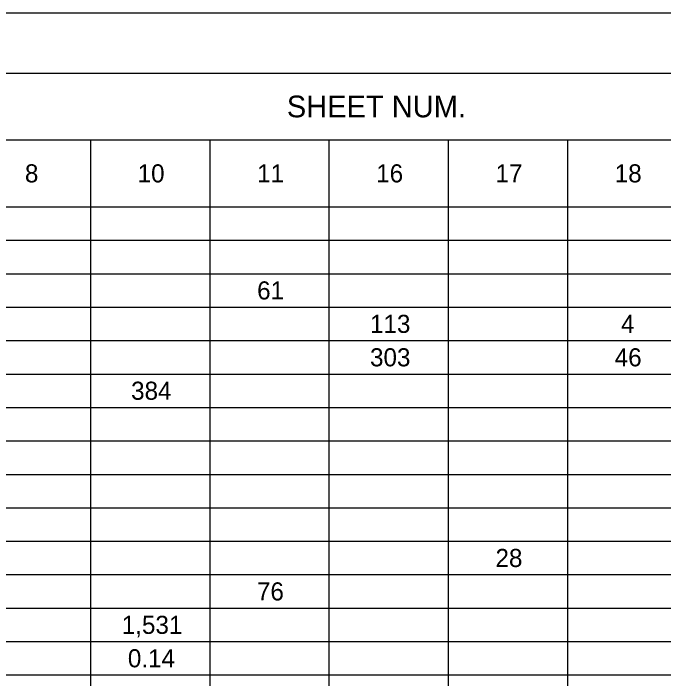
# Model space of a CAD drawing. Extents: x 0 to 44.3, y 0 to 22.
# Drawn here: x 5.16 to 10.6, y 16.43 to 22 of the extents above; entities that cross this region are included whole.
import ezdxf

# ---------------------------------------------------------------- set-up
doc = ezdxf.new("R2010")
doc.units = 0
for name, color, linetype in [('SH_Border', 7, 'Continuous'), ('SH_Cut_Line', 7, 'Continuous'), ('SH_Text', 7, 'Continuous')]:
    doc.layers.add(name, color=color, linetype=linetype)

msp = doc.modelspace()

# ---------------------------------------------------------------- linework, layer by layer
at = {"layer": 'SH_Border'}
msp.add_lwpolyline([(1.5, 21.5), (33.5, 21.5), (33.5, 0.5), (1.5, 0.5)], close=True, dxfattribs=at)
at = {"layer": 'SH_Cut_Line'}
msp.add_lwpolyline([(0, 0), (34, 0), (34, 22), (0, 22)], close=True, dxfattribs=at)
at = {"layer": 'SH_Text'}
for p, q in [((1.5, 21.5), (32, 21.5)), ((1.5, 20.94), (15.7846, 20.94)), ((5.8034, 20.94), (5.8034, 0.5)), ((6.8015, 20.94), (6.8015, 0.5)), ((7.7996, 20.94), (7.7996, 0.5)), ((8.7977, 20.94), (8.7977, 0.5)), ((9.7959, 20.94), (9.7959, 0.5)), ((1.5, 20.38), (32, 20.38)), ((1.5, 20.1), (32, 20.1)), ((1.5, 19.82), (32, 19.82)), ((1.5, 19.54), (32, 19.54)), ((1.5, 19.26), (32, 19.26)), ((1.5, 18.98), (32, 18.98)), ((1.5, 18.7), (32, 18.7)), ((1.5, 18.42), (32, 18.42)), ((1.5, 18.14), (32, 18.14)), ((1.5, 17.86), (32, 17.86)), ((1.5, 17.58), (32, 17.58)), ((1.5, 17.3), (32, 17.3)), ((1.5, 17.02), (32, 17.02)), ((1.5, 16.74), (32, 16.74)), ((1.5, 16.46), (32, 16.46))]:
    msp.add_line(p, q, dxfattribs=at)

# ---------------------------------------------------------------- texts
for s, height, p in [('SHEET NUM.', 0.18184, (7.4467, 21.1291)), ('8', 0.1515, (5.2546, 20.5842)), ('10', 0.15153, (6.198, 20.5842)), ('11', 0.15153, (7.1982, 20.5842)), ('16', 0.15153, (8.1948, 20.5842)), ('17', 0.15153, (9.1936, 20.5842)), ('18', 0.15153, (10.1912, 20.5842)), ('61', 0.15153, (7.1982, 19.6042)), ('113', 0.15153, (8.143, 19.3242)), ('4', 0.1515, (10.2439, 19.3242)), ('303', 0.15153, (8.143, 19.0442)), ('46', 0.15153, (10.191, 19.0442)), ('384', 0.15153, (6.1433, 18.7642)), ('28', 0.15153, (9.1931, 17.3642)), ('76', 0.15153, (7.1966, 17.0842)), ('1,531', 0.15153, (6.0653, 16.8042)), ('0.14', 0.15153, (6.1163, 16.5242))]:
    msp.add_text(s, height=height, dxfattribs=at).set_placement(p)

doc.saveas('drawing.dxf')
